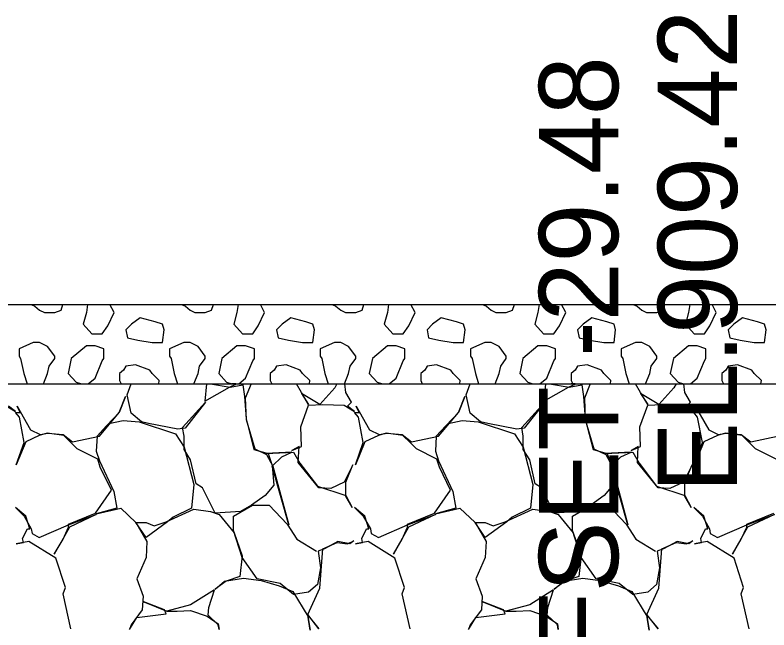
# Model space of a CAD drawing. Extents: x -26 to 4781, y -31 to 24738.
# Drawn here: x 2261.91 to 2271.42, y 8004.89 to 8012.65 of the extents above; entities that cross this region are included whole.
import ezdxf

# ---------------------------------------------------------------- set-up
doc = ezdxf.new("R2010")
doc.units = 0
for name, color, linetype in [('DESIGN - TRANSPORTATION - Proposed Layout Patterning', 7, 'Continuous'), ('DESIGN - TYPICAL - Subgrade Tie Text', 7, 'Continuous'), ('GEOTECHNICAL – SCRATCH – Level 1', 7, 'Continuous')]:
    doc.layers.add(name, color=color, linetype=linetype)

msp = doc.modelspace()

# ---------------------------------------------------------------- linework, layer by layer
at = {"layer": 'DESIGN - TRANSPORTATION - Proposed Layout Patterning'}
for p, q in [((2262.8226, 8009), (2262.8073, 8008.9006)), ((2264.7226, 8009), (2264.7073, 8008.9006)), ((2266.6226, 8009), (2266.6073, 8008.9006)), ((2268.5226, 8009), (2268.5073, 8008.9006)), ((2270.4226, 8009), (2270.4073, 8008.9006)), ((2262.8073, 8008.4806), (2262.6173, 8008.3206)), ((2264.7073, 8008.4806), (2264.5173, 8008.3206)), ((2266.6073, 8008.4806), (2266.4173, 8008.3206)), ((2268.5073, 8008.4806), (2268.3173, 8008.3206)), ((2270.4073, 8008.4806), (2270.2173, 8008.3206)), ((2261.9573, 8008.3506), (2261.9773, 8008.3206)), ((2263.8573, 8008.3506), (2263.8773, 8008.3206)), ((2265.7573, 8008.3506), (2265.7773, 8008.3206)), ((2267.6573, 8008.3506), (2267.6773, 8008.3206)), ((2269.5573, 8008.3506), (2269.5773, 8008.3206))]:
    msp.add_line(p, q, dxfattribs=at)
for points in [[(2262.1088, 8009), (2262.1573, 8008.9806), (2262.2173, 8008.9306)], [(2262.2173, 8008.9306), (2262.2773, 8008.9006), (2262.4073, 8008.9006), (2262.4873, 8008.9306), (2262.5104, 8009)], [(2262.8073, 8008.9006), (2262.7673, 8008.7506), (2262.8773, 8008.6306), (2263.0073, 8008.6306), (2263.0773, 8008.7306), (2263.1573, 8008.9006), (2263.1042, 8009)], [(2264.0088, 8009), (2264.0573, 8008.9806), (2264.1173, 8008.9306)], [(2264.1173, 8008.9306), (2264.1773, 8008.9006), (2264.3073, 8008.9006), (2264.3873, 8008.9306), (2264.4104, 8009)], [(2264.7073, 8008.9006), (2264.6673, 8008.7506), (2264.7773, 8008.6306), (2264.9073, 8008.6306), (2264.9773, 8008.7306), (2265.0573, 8008.9006), (2265.0042, 8009)], [(2265.9088, 8009), (2265.9573, 8008.9806), (2266.0173, 8008.9306)], [(2266.0173, 8008.9306), (2266.0773, 8008.9006), (2266.2073, 8008.9006), (2266.2873, 8008.9306), (2266.3104, 8009)], [(2266.6073, 8008.9006), (2266.5673, 8008.7506), (2266.6773, 8008.6306), (2266.8073, 8008.6306), (2266.8773, 8008.7306), (2266.9573, 8008.9006), (2266.9042, 8009)], [(2267.8088, 8009), (2267.8573, 8008.9806), (2267.9173, 8008.9306)], [(2267.9173, 8008.9306), (2267.9773, 8008.9006), (2268.1073, 8008.9006), (2268.1873, 8008.9306), (2268.2104, 8009)], [(2268.5073, 8008.9006), (2268.4673, 8008.7506), (2268.5773, 8008.6306), (2268.7073, 8008.6306), (2268.7773, 8008.7306), (2268.8573, 8008.9006), (2268.8042, 8009)], [(2269.7088, 8009), (2269.7573, 8008.9806), (2269.8173, 8008.9306)], [(2269.8173, 8008.9306), (2269.8773, 8008.9006), (2270.0073, 8008.9006), (2270.0873, 8008.9306), (2270.1104, 8009)], [(2270.4073, 8008.9006), (2270.3673, 8008.7506), (2270.4773, 8008.6306), (2270.6073, 8008.6306), (2270.6773, 8008.7306), (2270.7573, 8008.9006), (2270.7042, 8009)], [(2263.7673, 8008.7506), (2263.6773, 8008.7806), (2263.4873, 8008.8306), (2263.3773, 8008.7506), (2263.3073, 8008.6806), (2263.3273, 8008.5806), (2263.4573, 8008.5506), (2263.6373, 8008.5206), (2263.7673, 8008.5206), (2263.7873, 8008.6806), (2263.7673, 8008.7506)], [(2265.6673, 8008.7506), (2265.5773, 8008.7806), (2265.3873, 8008.8306), (2265.2773, 8008.7506), (2265.2073, 8008.6806), (2265.2273, 8008.5806), (2265.3573, 8008.5506), (2265.5373, 8008.5206), (2265.6673, 8008.5206), (2265.6873, 8008.6806), (2265.6673, 8008.7506)], [(2267.5673, 8008.7506), (2267.4773, 8008.7806), (2267.2873, 8008.8306), (2267.1773, 8008.7506), (2267.1073, 8008.6806), (2267.1273, 8008.5806), (2267.2573, 8008.5506), (2267.4373, 8008.5206), (2267.5673, 8008.5206), (2267.5873, 8008.6806), (2267.5673, 8008.7506)], [(2269.4673, 8008.7506), (2269.3773, 8008.7806), (2269.1873, 8008.8306), (2269.0773, 8008.7506), (2269.0073, 8008.6806), (2269.0273, 8008.5806), (2269.1573, 8008.5506), (2269.3373, 8008.5206), (2269.4673, 8008.5206), (2269.4873, 8008.6806), (2269.4673, 8008.7506)], [(2271.3673, 8008.7506), (2271.2773, 8008.7806), (2271.0873, 8008.8306), (2270.9773, 8008.7506), (2270.9073, 8008.6806), (2270.9273, 8008.5806), (2271.0573, 8008.5506), (2271.2373, 8008.5206), (2271.3673, 8008.5206), (2271.3873, 8008.6806), (2271.3673, 8008.7506)], [(2262.2173, 8008.5206), (2262.1573, 8008.5206), (2262.1373, 8008.5206), (2261.9573, 8008.4406), (2261.9573, 8008.3506)], [(2262.4073, 8008.3206), (2262.4073, 8008.3506), (2262.3173, 8008.4706), (2262.2173, 8008.5206)], [(2264.1173, 8008.5206), (2264.0573, 8008.5206), (2264.0373, 8008.5206), (2263.8573, 8008.4406), (2263.8573, 8008.3506)], [(2264.3073, 8008.3206), (2264.3073, 8008.3506), (2264.2173, 8008.4706), (2264.1173, 8008.5206)], [(2266.0173, 8008.5206), (2265.9573, 8008.5206), (2265.9373, 8008.5206), (2265.7573, 8008.4406), (2265.7573, 8008.3506)], [(2266.2073, 8008.3206), (2266.2073, 8008.3506), (2266.1173, 8008.4706), (2266.0173, 8008.5206)], [(2267.9173, 8008.5206), (2267.8573, 8008.5206), (2267.8373, 8008.5206), (2267.6573, 8008.4406), (2267.6573, 8008.3506)], [(2268.1073, 8008.3206), (2268.1073, 8008.3506), (2268.0173, 8008.4706), (2267.9173, 8008.5206)], [(2269.8173, 8008.5206), (2269.7573, 8008.5206), (2269.7373, 8008.5206), (2269.5573, 8008.4406), (2269.5573, 8008.3506)], [(2270.0073, 8008.3206), (2270.0073, 8008.3506), (2269.9173, 8008.4706), (2269.8173, 8008.5206)], [(2263.0273, 8008.3206), (2263.0273, 8008.4406), (2262.9173, 8008.4806), (2262.8073, 8008.4806)], [(2264.9273, 8008.3206), (2264.9273, 8008.4406), (2264.8173, 8008.4806), (2264.7073, 8008.4806)], [(2266.8273, 8008.3206), (2266.8273, 8008.4406), (2266.7173, 8008.4806), (2266.6073, 8008.4806)], [(2268.7273, 8008.3206), (2268.7273, 8008.4406), (2268.6173, 8008.4806), (2268.5073, 8008.4806)], [(2270.6273, 8008.3206), (2270.6273, 8008.4406), (2270.5173, 8008.4806), (2270.4073, 8008.4806)], [(2261.9773, 8008.3206), (2262.0173, 8008.1306), (2262.0585, 8008)], [(2262.265, 8008), (2262.3173, 8008.1306), (2262.3373, 8008.2206), (2262.4073, 8008.3206)], [(2262.6173, 8008.3206), (2262.5773, 8008.1306), (2262.6773, 8008.0206), (2262.7442, 8008)], [(2262.831, 8008), (2262.9173, 8008.0706), (2263.0073, 8008.2906), (2263.0273, 8008.3206)], [(2263.8773, 8008.3206), (2263.9173, 8008.1306), (2263.9585, 8008)], [(2264.165, 8008), (2264.2173, 8008.1306), (2264.2373, 8008.2206), (2264.3073, 8008.3206)], [(2264.5173, 8008.3206), (2264.4773, 8008.1306), (2264.5773, 8008.0206), (2264.6442, 8008)], [(2264.731, 8008), (2264.8173, 8008.0706), (2264.9073, 8008.2906), (2264.9273, 8008.3206)], [(2265.7773, 8008.3206), (2265.8173, 8008.1306), (2265.8585, 8008)], [(2266.065, 8008), (2266.1173, 8008.1306), (2266.1373, 8008.2206), (2266.2073, 8008.3206)], [(2266.4173, 8008.3206), (2266.3773, 8008.1306), (2266.4773, 8008.0206), (2266.5442, 8008)], [(2266.631, 8008), (2266.7173, 8008.0706), (2266.8073, 8008.2906), (2266.8273, 8008.3206)], [(2267.6773, 8008.3206), (2267.7173, 8008.1306), (2267.7585, 8008)], [(2267.965, 8008), (2268.0173, 8008.1306), (2268.0373, 8008.2206), (2268.1073, 8008.3206)], [(2268.3173, 8008.3206), (2268.2773, 8008.1306), (2268.3773, 8008.0206), (2268.4442, 8008)], [(2268.531, 8008), (2268.6173, 8008.0706), (2268.7073, 8008.2906), (2268.7273, 8008.3206)], [(2269.5773, 8008.3206), (2269.6173, 8008.1306), (2269.6585, 8008)], [(2269.865, 8008), (2269.9173, 8008.1306), (2269.9373, 8008.2206), (2270.0073, 8008.3206)], [(2270.2173, 8008.3206), (2270.1773, 8008.1306), (2270.2773, 8008.0206), (2270.3442, 8008)], [(2270.431, 8008), (2270.5173, 8008.0706), (2270.6073, 8008.2906), (2270.6273, 8008.3206)], [(2263.6073, 8008.1706), (2263.4273, 8008.2406), (2263.3073, 8008.2206), (2263.2773, 8008.1706), (2263.2273, 8008.1306), (2263.2273, 8008.0406), (2263.2476, 8008)], [(2265.5073, 8008.1706), (2265.3273, 8008.2406), (2265.2073, 8008.2206), (2265.1773, 8008.1706), (2265.1273, 8008.1306), (2265.1273, 8008.0406), (2265.1476, 8008)], [(2267.4073, 8008.1706), (2267.2273, 8008.2406), (2267.1073, 8008.2206), (2267.0773, 8008.1706), (2267.0273, 8008.1306), (2267.0273, 8008.0406), (2267.0476, 8008)], [(2269.3073, 8008.1706), (2269.1273, 8008.2406), (2269.0073, 8008.2206), (2268.9773, 8008.1706), (2268.9273, 8008.1306), (2268.9273, 8008.0406), (2268.9476, 8008)], [(2271.2073, 8008.1706), (2271.0273, 8008.2406), (2270.9073, 8008.2206), (2270.8773, 8008.1706), (2270.8273, 8008.1306), (2270.8273, 8008.0406), (2270.8476, 8008)], [(2263.7218, 8008), (2263.7273, 8008.0406), (2263.6373, 8008.1306), (2263.6073, 8008.1706)], [(2265.6218, 8008), (2265.6273, 8008.0406), (2265.5373, 8008.1306), (2265.5073, 8008.1706)], [(2267.5218, 8008), (2267.5273, 8008.0406), (2267.4373, 8008.1306), (2267.4073, 8008.1706)], [(2269.4218, 8008), (2269.4273, 8008.0406), (2269.3373, 8008.1306), (2269.3073, 8008.1706)], [(2271.3218, 8008), (2271.3273, 8008.0406), (2271.2373, 8008.1306), (2271.2073, 8008.1706)], [(2264.3748, 8008), (2264.6225, 8007.9587), (2264.7825, 8007.9887), (2264.8025, 8007.8387), (2264.8225, 8007.5587), (2264.9225, 8007.1687), (2265.1025, 8007.1187), (2265.1525, 8006.9687), (2265.1725, 8006.7187), (2265.0625, 8006.5887), (2264.8925, 8006.4687), (2264.7525, 8006.3887), (2264.4325, 8006.3687), (2264.2725, 8006.6887), (2264.1925, 8006.7387), (2264.1225, 8007.0387), (2264.0425, 8007.1687), (2264.0425, 8007.3387), (2264.0225, 8007.4487), (2264.3125, 8007.7687), (2264.0525, 8007.4387), (2263.9625, 8007.4287), (2263.5925, 8007.4987), (2263.5025, 8007.5187), (2263.3725, 8007.6287), (2263.3225, 8007.8587), (2263.3725, 8007.9987), (2263.3721, 8008)], [(2264.3219, 8008), (2264.3225, 8007.9987), (2264.3025, 8007.7787), (2264.6125, 8007.9587), (2264.7033, 8008)], [(2264.6947, 8008), (2264.6925, 8007.9987), (2264.6451, 8008)], [(2264.888, 8008), (2264.8125, 8007.8187), (2264.8225, 8007.5487), (2264.9325, 8007.1787), (2265.0825, 8007.1087), (2265.1625, 8006.9587), (2265.3625, 8006.2187), (2265.1525, 8006.9587), (2265.2725, 8007.0787), (2265.4025, 8007.1387), (2265.0725, 8007.1187), (2265.4225, 8007.1387), (2265.5025, 8006.9987), (2265.7225, 8006.7087), (2266.0825, 8006.5887), (2266.1625, 8006.4387), (2266.0825, 8006.5787), (2266.0825, 8006.7587), (2266.1725, 8006.9787), (2266.0625, 8006.7587), (2265.8925, 8006.6787), (2265.7425, 8006.6887), (2265.4825, 8007.0087), (2265.4925, 8007.2087), (2265.4025, 8007.1587), (2265.5225, 8007.2087), (2265.5125, 8007.4587), (2265.6125, 8007.7287), (2265.7925, 8007.7387), (2266.0625, 8007.7287), (2266.1925, 8007.6487), (2266.1025, 8007.7187), (2266.1525, 8007.7687), (2266.0825, 8007.8887), (2266.068, 8008)], [(2265.9698, 8008), (2265.9425, 8007.9487), (2265.7525, 8007.7387), (2265.5225, 8007.8787), (2265.6125, 8007.7387), (2265.5225, 8007.8887), (2265.4596, 8008)], [(2268.6548, 8008), (2268.9025, 8007.9587), (2269.0625, 8007.9887), (2269.0825, 8007.8387), (2269.1025, 8007.5587), (2269.2025, 8007.1687), (2269.3825, 8007.1187), (2269.4325, 8006.9687), (2269.4525, 8006.7187), (2269.3425, 8006.5887), (2269.1725, 8006.4687), (2269.0325, 8006.3887), (2268.7125, 8006.3687), (2268.5525, 8006.6887), (2268.4725, 8006.7387), (2268.4025, 8007.0387), (2268.3225, 8007.1687), (2268.3225, 8007.3387), (2268.3025, 8007.4487), (2268.5925, 8007.7687), (2268.3325, 8007.4387), (2268.2425, 8007.4287), (2267.8725, 8007.4987), (2267.7825, 8007.5187), (2267.6525, 8007.6287), (2267.6025, 8007.8587), (2267.6525, 8007.9987), (2267.6521, 8008)], [(2268.6019, 8008), (2268.6025, 8007.9987), (2268.5825, 8007.7787), (2268.8925, 8007.9587), (2268.9833, 8008)], [(2268.9747, 8008), (2268.9725, 8007.9987), (2268.9251, 8008)], [(2269.168, 8008), (2269.0925, 8007.8187), (2269.1025, 8007.5487), (2269.2125, 8007.1787), (2269.3625, 8007.1087), (2269.4425, 8006.9587), (2269.6425, 8006.2187), (2269.4325, 8006.9587), (2269.5525, 8007.0787), (2269.6825, 8007.1387), (2269.3525, 8007.1187), (2269.7025, 8007.1387), (2269.7825, 8006.9987), (2270.0025, 8006.7087), (2270.3625, 8006.5887), (2270.4425, 8006.4387), (2270.3625, 8006.5787), (2270.3625, 8006.7587), (2270.4525, 8006.9787), (2270.3425, 8006.7587), (2270.1725, 8006.6787), (2270.0225, 8006.6887), (2269.7625, 8007.0087), (2269.7725, 8007.2087), (2269.6825, 8007.1587), (2269.8025, 8007.2087), (2269.7925, 8007.4587), (2269.8925, 8007.7287), (2270.0725, 8007.7387), (2270.3425, 8007.7287), (2270.4725, 8007.6487), (2270.3825, 8007.7187), (2270.4325, 8007.7687), (2270.3625, 8007.8887), (2270.348, 8008)], [(2270.2498, 8008), (2270.2225, 8007.9487), (2270.0325, 8007.7387), (2269.8025, 8007.8787), (2269.8925, 8007.7387), (2269.8025, 8007.8887), (2269.7396, 8008)], [(2262.6125, 8004.9087), (2262.5125, 8005.3487), (2262.5425, 8005.4287), (2262.4225, 8005.7987), (2262.0825, 8006.0087), (2261.9225, 8005.9787), (2262.0125, 8005.9987), (2262.0025, 8006.0487), (2262.0625, 8006.1687), (2262.0925, 8006.1687), (2262.0425, 8006.3287), (2261.9125, 8006.4387), (2262.0225, 8006.3287), (2262.1125, 8006.1687), (2262.1225, 8006.1087), (2262.2125, 8006.0587), (2262.5825, 8006.2187), (2262.9325, 8006.3487), (2262.5925, 8006.1887), (2262.5125, 8006.0487), (2262.4025, 8005.8487), (2262.5125, 8006.0387), (2262.5825, 8006.1887), (2262.5825, 8006.2287), (2262.9225, 8006.3687), (2263.1225, 8006.6587), (2262.9825, 8006.9487), (2262.9525, 8007.0487), (2262.6925, 8007.1787), (2262.6125, 8007.2587), (2262.5225, 8007.3487), (2262.3125, 8007.3787), (2262.2125, 8007.3487), (2262.0425, 8007.2687), (2261.9225, 8006.9787), (2262.0225, 8007.2587), (2261.9625, 8007.5787), (2261.9125, 8007.6387), (2261.9725, 8007.6387), (2261.9325, 8007.7187), (2262.1025, 8007.4187), (2262.2225, 8007.3587), (2262.3225, 8007.3787), (2262.5125, 8007.3587), (2262.6325, 8007.2687), (2262.9725, 8007.3387), (2263.2225, 8007.6387), (2263.3025, 8007.8387), (2263.2225, 8007.6387), (2263.0625, 8007.4687), (2262.9425, 8007.3387), (2262.9325, 8007.1487), (2262.9725, 8007.0287), (2263.1525, 8006.6387), (2263.1925, 8006.4287), (2262.9325, 8006.3587), (2263.2425, 8006.4287), (2263.4325, 8006.2487), (2263.5725, 8006.0087), (2263.5625, 8005.8087), (2263.4425, 8005.5387), (2263.5225, 8005.3187), (2263.5125, 8005.1487), (2263.3725, 8004.9587), (2263.3525, 8004.8987), (2263.4425, 8005.0487), (2263.8125, 8005.0987), (2263.7925, 8005.1487), (2263.5325, 8005.2487), (2263.8225, 8005.1287), (2263.9525, 8005.1287), (2264.1225, 8005.1387), (2264.3325, 8005.0687), (2264.4725, 8004.9687), (2264.4825, 8004.8987), (2264.4725, 8004.9587), (2264.3425, 8005.0787), (2264.3525, 8005.1787), (2264.4225, 8005.3987), (2264.1225, 8005.2087), (2263.8225, 8005.1287)], [(2266.8925, 8004.9087), (2266.7925, 8005.3487), (2266.8225, 8005.4287), (2266.7025, 8005.7987), (2266.3625, 8006.0087), (2266.2025, 8005.9787), (2266.2925, 8005.9987), (2266.2825, 8006.0487), (2266.3425, 8006.1687), (2266.3725, 8006.1687), (2266.3225, 8006.3287), (2266.1925, 8006.4387), (2266.3025, 8006.3287), (2266.3925, 8006.1687), (2266.4025, 8006.1087), (2266.4925, 8006.0587), (2266.8625, 8006.2187), (2267.2125, 8006.3487), (2266.8725, 8006.1887), (2266.7925, 8006.0487), (2266.6825, 8005.8487), (2266.7925, 8006.0387), (2266.8625, 8006.1887), (2266.8625, 8006.2287), (2267.2025, 8006.3687), (2267.4025, 8006.6587), (2267.2625, 8006.9487), (2267.2325, 8007.0487), (2266.9725, 8007.1787), (2266.8925, 8007.2587), (2266.8025, 8007.3487), (2266.5925, 8007.3787), (2266.4925, 8007.3487), (2266.3225, 8007.2687), (2266.2025, 8006.9787), (2266.3025, 8007.2587), (2266.2425, 8007.5787), (2266.1925, 8007.6387), (2266.2525, 8007.6387), (2266.2125, 8007.7187), (2266.3825, 8007.4187), (2266.5025, 8007.3587), (2266.6025, 8007.3787), (2266.7925, 8007.3587), (2266.9125, 8007.2687), (2267.2525, 8007.3387), (2267.5025, 8007.6387), (2267.5825, 8007.8387), (2267.5025, 8007.6387), (2267.3425, 8007.4687), (2267.2225, 8007.3387), (2267.2125, 8007.1487), (2267.2525, 8007.0287), (2267.4325, 8006.6387), (2267.4725, 8006.4287), (2267.2125, 8006.3587), (2267.5225, 8006.4287), (2267.7125, 8006.2487), (2267.8525, 8006.0087), (2267.8425, 8005.8087), (2267.7225, 8005.5387), (2267.8025, 8005.3187), (2267.7925, 8005.1487), (2267.6525, 8004.9587), (2267.6325, 8004.8987), (2267.7225, 8005.0487), (2268.0925, 8005.0987), (2268.0725, 8005.1487), (2267.8125, 8005.2487), (2268.1025, 8005.1287), (2268.2325, 8005.1287), (2268.4025, 8005.1387), (2268.6125, 8005.0687), (2268.7525, 8004.9687), (2268.7625, 8004.8987), (2268.7525, 8004.9587), (2268.6225, 8005.0787), (2268.6325, 8005.1787), (2268.7025, 8005.3987), (2268.4025, 8005.2087), (2268.1025, 8005.1287)], [(2261.7825, 8007.7287), (2261.9125, 8007.6487), (2261.8225, 8007.7187)], [(2271.5125, 8007.0487), (2271.2525, 8007.1787), (2271.1725, 8007.2587), (2271.0825, 8007.3487), (2270.8725, 8007.3787), (2270.7725, 8007.3487), (2270.6025, 8007.2687), (2270.4825, 8006.9787), (2270.5825, 8007.2587), (2270.5225, 8007.5787), (2270.4725, 8007.6387), (2270.5325, 8007.6387), (2270.4925, 8007.7187), (2270.6625, 8007.4187), (2270.7825, 8007.3587), (2270.8825, 8007.3787), (2271.0725, 8007.3587), (2271.1925, 8007.2687), (2271.5325, 8007.3387)], [(2263.0925, 8007.4987), (2263.2725, 8007.5387), (2263.4725, 8007.5187), (2263.9325, 8007.3687), (2264.0425, 8007.1987), (2264.1625, 8006.7287), (2264.1325, 8006.4287), (2263.9025, 8006.3187), (2263.8325, 8006.2587), (2263.5625, 8006.0587), (2263.4325, 8006.2487), (2263.5625, 8006.2487), (2263.6625, 8006.2087), (2263.8125, 8006.2587), (2264.1625, 8006.4187), (2264.3725, 8006.3887), (2264.4825, 8006.3487), (2264.6725, 8006.1187), (2264.7725, 8005.8287), (2264.7425, 8005.5687), (2264.5725, 8005.5087), (2264.4325, 8005.4087), (2264.5525, 8005.5087), (2264.7925, 8005.5487), (2265.0125, 8005.5187), (2265.2425, 8005.4487), (2265.4125, 8005.3787), (2265.6025, 8005.0687), (2265.6325, 8004.8887), (2265.6025, 8005.0787), (2265.7425, 8004.9087), (2265.6025, 8005.0887), (2265.7525, 8005.4187), (2265.7925, 8005.9187), (2265.9725, 8005.9987), (2266.1025, 8005.9787), (2266.1825, 8006.0187), (2266.1325, 8005.9787), (2265.9825, 8006.0087), (2265.8125, 8005.9187), (2265.7325, 8005.8887), (2265.7625, 8005.6787), (2265.7225, 8005.4687), (2265.6125, 8005.3687), (2265.4225, 8005.3387), (2265.2525, 8005.4787), (2264.9625, 8005.5387), (2264.7725, 8005.8087), (2264.6625, 8006.1487), (2264.6625, 8006.3287), (2264.9025, 8006.4687), (2265.1125, 8006.4687), (2265.3425, 8006.2287), (2265.4625, 8006.0387), (2265.7125, 8005.8887)], [(2267.3725, 8007.4987), (2267.5525, 8007.5387), (2267.7525, 8007.5187), (2268.2125, 8007.3687), (2268.3225, 8007.1987), (2268.4425, 8006.7287), (2268.4125, 8006.4287), (2268.1825, 8006.3187), (2268.1125, 8006.2587), (2267.8425, 8006.0587), (2267.7125, 8006.2487), (2267.8425, 8006.2487), (2267.9425, 8006.2087), (2268.0925, 8006.2587), (2268.4425, 8006.4187), (2268.6525, 8006.3887), (2268.7625, 8006.3487), (2268.9525, 8006.1187), (2269.0525, 8005.8287), (2269.0225, 8005.5687), (2268.8525, 8005.5087), (2268.7125, 8005.4087), (2268.8325, 8005.5087), (2269.0725, 8005.5487), (2269.2925, 8005.5187), (2269.5225, 8005.4487), (2269.6925, 8005.3787), (2269.8825, 8005.0687), (2269.9125, 8004.8887), (2269.8825, 8005.0787), (2270.0225, 8004.9087), (2269.8825, 8005.0887), (2270.0325, 8005.4187), (2270.0725, 8005.9187), (2270.2525, 8005.9987), (2270.3825, 8005.9787), (2270.4625, 8006.0187), (2270.4125, 8005.9787), (2270.2625, 8006.0087), (2270.0925, 8005.9187), (2270.0125, 8005.8887), (2270.0425, 8005.6787), (2270.0025, 8005.4687), (2269.8925, 8005.3687), (2269.7025, 8005.3387), (2269.5325, 8005.4787), (2269.2425, 8005.5387), (2269.0525, 8005.8087), (2268.9425, 8006.1487), (2268.9425, 8006.3287), (2269.1825, 8006.4687), (2269.3925, 8006.4687), (2269.6225, 8006.2287), (2269.7425, 8006.0387), (2269.9925, 8005.8887)], [(2271.1725, 8004.9087), (2271.0725, 8005.3487), (2271.1025, 8005.4287), (2270.9825, 8005.7987), (2270.6425, 8006.0087), (2270.4825, 8005.9787), (2270.5725, 8005.9987), (2270.5625, 8006.0487), (2270.6225, 8006.1687), (2270.6525, 8006.1687), (2270.6025, 8006.3287), (2270.4725, 8006.4387), (2270.5825, 8006.3287), (2270.6725, 8006.1687), (2270.6825, 8006.1087), (2270.7725, 8006.0587), (2271.1425, 8006.2187), (2271.4925, 8006.3487), (2271.1525, 8006.1887), (2271.0725, 8006.0487), (2270.9625, 8005.8487), (2271.0725, 8006.0387), (2271.1425, 8006.1887), (2271.1425, 8006.2287), (2271.4825, 8006.3687)]]:
    msp.add_lwpolyline(points, dxfattribs=at)
at = {"layer": 'GEOTECHNICAL – SCRATCH – Level 1'}
for p, q in [((2245.2557, 8009), (2327.7679, 8009)), ((2242.2557, 8008), (2321.5449, 8008))]:
    msp.add_line(p, q, dxfattribs=at)

# ---------------------------------------------------------------- texts
at = {"layer": 'DESIGN - TYPICAL - Subgrade Tie Text'}
for s, p in [('EL.909.42', (2271.0196, 8006.6236)), ('OFFSET -29.48', (2269.5196, 8002.6962))]:
    msp.add_text(s, height=1, rotation=90, dxfattribs=at).set_placement(p)

doc.saveas('drawing.dxf')
